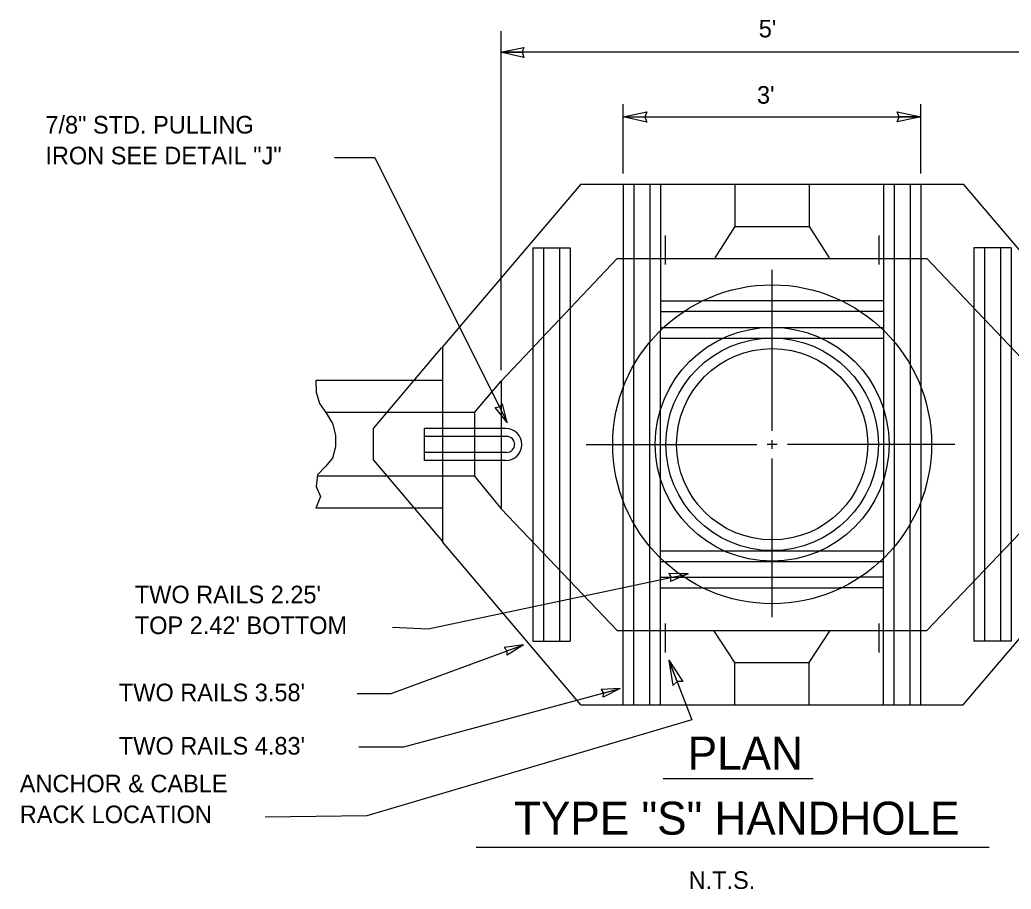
# Model space of a CAD drawing. Extents: x 19188 to 19495, y 20866 to 21061.
# Drawn here: x 19188.42 to 19235.64, y 21018.73 to 21060.13 of the extents above; entities that cross this region are included whole.
import ezdxf

# ---------------------------------------------------------------- set-up
doc = ezdxf.new("R2010")
doc.units = 0
doc.layers.add('G-ANNO-NOTE', color=7, linetype='Continuous')

msp = doc.modelspace()

# ---------------------------------------------------------------- linework, layer by layer
at = {"layer": 'G-ANNO-NOTE'}
for p, q in [((19211.34, 21043.442), (19211.34, 21059.598)), ((19237.159, 21058.588), (19211.313, 21058.588)), ((19211.313, 21058.588), (19212.343, 21058.588)), ((19217.162, 21052.813), (19217.162, 21056.117)), ((19231.337, 21052.813), (19231.337, 21056.117)), ((19217.162, 21055.513), (19231.339, 21055.513)), ((19217.162, 21055.513), (19218.193, 21055.513)), ((19231.339, 21055.513), (19230.308, 21055.513)), ((19215.137, 21052.314), (19208.556, 21044.556)), ((19215.137, 21052.314), (19233.362, 21052.314)), ((19217.162, 21052.314), (19217.162, 21042.53)), ((19217.668, 21052.314), (19217.668, 21043.681)), ((19218.427, 21052.314), (19218.427, 21044.776)), ((19218.934, 21052.314), (19218.934, 21045.31)), ((19222.477, 21052.314), (19222.477, 21050.289)), ((19226.021, 21052.314), (19226.021, 21050.289)), ((19229.565, 21052.314), (19229.565, 21045.365)), ((19230.071, 21052.314), (19230.071, 21044.776)), ((19230.83, 21052.314), (19230.83, 21043.737)), ((19231.337, 21052.314), (19231.337, 21042.699)), ((19233.362, 21052.314), (19239.943, 21044.556)), ((19222.477, 21050.289), (19221.524, 21048.795)), ((19222.477, 21050.289), (19226.021, 21050.289)), ((19226.021, 21050.289), (19226.974, 21048.795)), ((19219.162, 21049.855), (19219.162, 21048.481)), ((19229.337, 21049.855), (19229.337, 21048.481)), ((19212.859, 21049.277), (19212.859, 21030.545)), ((19212.859, 21049.277), (19214.631, 21049.277)), ((19213.365, 21049.277), (19213.365, 21030.545)), ((19214.125, 21049.277), (19214.125, 21030.545)), ((19214.631, 21049.277), (19214.631, 21030.545)), ((19233.868, 21049.277), (19233.868, 21030.545)), ((19235.639, 21049.277), (19233.868, 21049.277)), ((19234.374, 21049.277), (19234.374, 21030.545)), ((19235.134, 21049.277), (19235.134, 21030.545)), ((19235.639, 21049.277), (19235.639, 21030.545)), ((19216.873, 21048.77), (19211.34, 21042.927)), ((19216.873, 21048.77), (19231.626, 21048.77)), ((19231.626, 21048.77), (19237.159, 21042.927)), ((19218.934, 21046.745), (19220.93, 21046.745)), ((19227.554, 21046.745), (19220.961, 21046.745)), ((19229.565, 21046.745), (19227.615, 21046.745)), ((19218.934, 21046.239), (19220.023, 21046.239)), ((19228.431, 21046.239), (19220.023, 21046.239)), ((19229.565, 21046.239), (19228.462, 21046.239)), ((19218.934, 21045.48), (19229.565, 21045.48)), ((19229.565, 21045.365), (19229.565, 21034.474)), ((19218.934, 21034.502), (19218.934, 21045.31)), ((19218.934, 21044.974), (19229.565, 21044.974)), ((19205.265, 21040.677), (19208.527, 21044.521)), ((19208.556, 21044.556), (19208.556, 21035.275)), ((19218.427, 21035.063), (19218.427, 21044.748)), ((19230.071, 21044.776), (19230.071, 21035.007)), ((19217.668, 21036.158), (19217.668, 21043.681)), ((19230.83, 21043.737), (19230.83, 21036.158)), ((19208.556, 21042.949), (19202.518, 21042.949)), ((19210.075, 21041.43), (19211.34, 21042.927)), ((19211.34, 21042.927), (19211.34, 21036.845)), ((19217.162, 21037.253), (19217.162, 21042.53)), ((19231.337, 21042.699), (19231.337, 21037.169)), ((19210.075, 21041.43), (19203.026, 21041.43)), ((19210.075, 21041.43), (19210.075, 21038.393)), ((19205.265, 21039.158), (19205.265, 21040.677)), ((19211.57, 21040.67), (19207.678, 21040.67)), ((19207.678, 21040.67), (19207.678, 21039.152)), ((19211.611, 21040.291), (19207.678, 21040.291)), ((19211.991, 21039.911), (19211.991, 21039.911)), ((19212.33, 21039.911), (19212.33, 21039.911)), ((19211.611, 21039.532), (19207.678, 21039.532)), ((19205.265, 21039.158), (19208.546, 21035.286)), ((19211.571, 21039.152), (19207.678, 21039.152)), ((19210.075, 21038.393), (19202.638, 21038.393)), ((19210.075, 21038.393), (19211.34, 21036.845)), ((19208.556, 21036.874), (19202.518, 21036.874)), ((19217.162, 21027.508), (19217.162, 21037.253)), ((19231.337, 21027.508), (19231.337, 21037.169)), ((19211.34, 21036.845), (19216.873, 21031.052)), ((19237.159, 21036.845), (19231.626, 21031.052)), ((19217.668, 21027.508), (19217.668, 21036.158)), ((19230.83, 21027.508), (19230.83, 21036.13)), ((19215.137, 21027.508), (19208.556, 21035.275)), ((19218.427, 21027.508), (19218.427, 21035.063)), ((19230.071, 21027.508), (19230.071, 21035.007)), ((19233.362, 21027.508), (19239.943, 21035.275)), ((19218.934, 21034.849), (19229.565, 21034.849)), ((19218.934, 21027.508), (19218.934, 21034.502)), ((19218.934, 21034.343), (19229.565, 21034.343)), ((19229.565, 21027.508), (19229.565, 21034.474)), ((19218.934, 21033.583), (19220.053, 21033.583)), ((19220.083, 21033.583), (19228.401, 21033.583)), ((19229.565, 21033.583), (19228.401, 21033.583)), ((19218.934, 21033.077), (19220.93, 21033.077)), ((19220.961, 21033.077), (19227.463, 21033.077)), ((19229.565, 21033.077), (19227.463, 21033.077)), ((19219.162, 21031.379), (19219.162, 21030.005)), ((19229.337, 21031.379), (19229.337, 21030.005)), ((19216.873, 21031.052), (19231.626, 21031.052)), ((19222.477, 21029.533), (19221.476, 21031.05)), ((19226.021, 21029.533), (19227.022, 21031.05)), ((19212.859, 21030.545), (19214.631, 21030.545)), ((19235.639, 21030.545), (19233.868, 21030.545)), ((19222.477, 21029.533), (19226.021, 21029.533)), ((19222.477, 21027.508), (19222.477, 21029.533)), ((19226.021, 21027.508), (19226.021, 21029.533)), ((19215.137, 21027.508), (19233.362, 21027.508)), ((19219.061, 21024.01), (19226.209, 21024.01)), ((19210.162, 21020.74), (19234.591, 21020.74))]:
    msp.add_line(p, q, dxfattribs=at)
for points in [[(19212.344, 21058.588), (19212.434, 21058.341), (19211.313, 21058.588), (19212.432, 21058.823), (19212.344, 21058.588)], [(19218.193, 21055.514), (19218.283, 21055.267), (19217.162, 21055.513), (19218.28, 21055.749), (19218.193, 21055.514)], [(19230.307, 21055.513), (19230.217, 21055.759), (19231.339, 21055.513), (19230.22, 21055.278), (19230.307, 21055.513)], [(19203.401, 21053.581), (19205.324, 21053.581), (19211.631, 21040.961)], [(19224.25, 21048.229), (19224.25, 21040.565)], [(19202.518, 21042.949), (19202.542, 21042.407), (19202.687, 21041.854), (19203.026, 21041.381), (19203.317, 21040.909), (19203.462, 21040.356), (19203.462, 21039.804), (19203.317, 21039.252), (19202.978, 21038.858), (19202.59, 21038.464), (19202.542, 21037.912), (19202.735, 21037.438), (19202.518, 21036.874), (19202.518, 21036.874)], [(19215.396, 21039.911), (19223.531, 21039.911)], [(19224.499, 21039.911), (19224.016, 21039.911)], [(19224.25, 21040.116), (19224.25, 21039.695)], [(19232.967, 21039.911), (19224.983, 21039.911)], [(19224.25, 21039.246), (19224.25, 21031.686)], [(19206.177, 21031.211), (19207.869, 21031.134), (19220.253, 21033.75)], [(19204.485, 21028.055), (19206.1, 21028.055), (19212.407, 21030.364)], [(19219.34, 21029.644), (19220.437, 21026.803), (19204.949, 21022.219), (19200.11, 21022.155)], [(19204.562, 21025.516), (19206.715, 21025.516), (19217.022, 21028.286)]]:
    msp.add_lwpolyline(points, dxfattribs=at)
for points in [[(19211.406, 21041.851), (19211.262, 21041.698), (19211.631, 21040.961), (19211.062, 21041.677), (19211.262, 21041.698), (19211.631, 21040.961)], [(19219.335, 21033.758), (19219.446, 21033.579), (19220.253, 21033.75), (19219.416, 21033.381), (19219.446, 21033.579), (19220.253, 21033.75)], [(19211.497, 21030.241), (19211.633, 21030.081), (19212.407, 21030.364), (19211.632, 21029.879), (19211.633, 21030.081), (19212.407, 21030.364)], [(19219.525, 21028.434), (19219.736, 21028.618), (19219.34, 21029.644), (19220.003, 21028.621), (19219.736, 21028.618), (19219.34, 21029.644)], [(19216.105, 21028.244), (19216.226, 21028.072), (19217.022, 21028.286), (19216.207, 21027.872), (19216.226, 21028.072), (19217.022, 21028.286)]]:
    msp.add_lwpolyline(points, close=True, dxfattribs=at)
for radius in [7.594, 5.569, 5.062, 4.556]:
    msp.add_circle((19224.257, 21039.92), radius, dxfattribs=at)
for centre, radius, start, end in [((19211.57, 21039.911), 0.759, 0, 90), ((19211.611, 21039.911), 0.38, 0, 90), ((19211.571, 21039.911), 0.759, 270, 0), ((19211.611, 21039.911), 0.379, 270, 360)]:
    msp.add_arc(centre, radius, start, end, dxfattribs=at)

# ---------------------------------------------------------------- texts
for s, height, p in [("5'", 0.8379, (19223.62, 21059.295)), ("3'", 0.8379, (19223.535, 21056.14)), ('7/8" STD. PULLING ', 0.83785, (19189.635, 21054.718)), ('IRON SEE DETAIL "J"', 0.83785, (19189.635, 21053.252)), ("TWO RAILS 2.25'", 0.83785, (19193.895, 21032.347)), ("TOP 2.42' BOTTOM", 0.83785, (19193.895, 21030.88)), ("TWO RAILS 3.58'", 0.83786, (19193.136, 21027.681)), ('PLAN', 1.571, (19220.235, 21024.428)), ("TWO RAILS 4.83'", 0.83786, (19193.136, 21025.141)), ('ANCHOR & CABLE', 0.83786, (19188.414, 21023.344)), ('RACK LOCATION', 0.83786, (19188.414, 21021.877)), ('TYPE "S" HANDHOLE', 1.57098, (19211.963, 21021.329)), ('N.T.S.', 0.8379, (19220.279, 21018.744))]:
    msp.add_text(s, height=height, dxfattribs=at).set_placement(p)

doc.saveas('drawing.dxf')
